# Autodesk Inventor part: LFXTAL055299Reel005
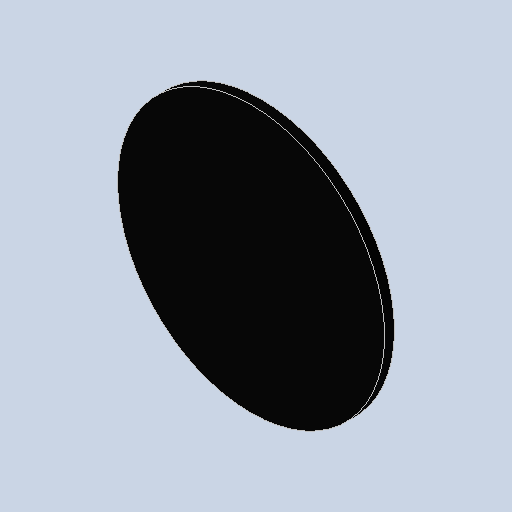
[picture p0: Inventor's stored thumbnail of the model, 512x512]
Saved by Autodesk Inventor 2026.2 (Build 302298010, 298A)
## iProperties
Created: 2026-10
Part Number: LFXTAL055299Reel005
Material: Générique
Document SubType Name: Modeling
Designer: mel
Density: 1 g/cm^3
Appearance: Par défaut
Author: mel
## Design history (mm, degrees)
feature "Base1"
node "Solide1"
